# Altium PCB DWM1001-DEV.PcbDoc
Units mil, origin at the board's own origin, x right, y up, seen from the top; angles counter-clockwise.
Board outline 1692.91 x 2125.98 mil, 4 copper layers (Top Layer, Signal Layer 1, Signal Layer 2, Bottom Layer), stack 30.634 mil thick; 85 components, 72 nets, 323 pads, 369 vias.
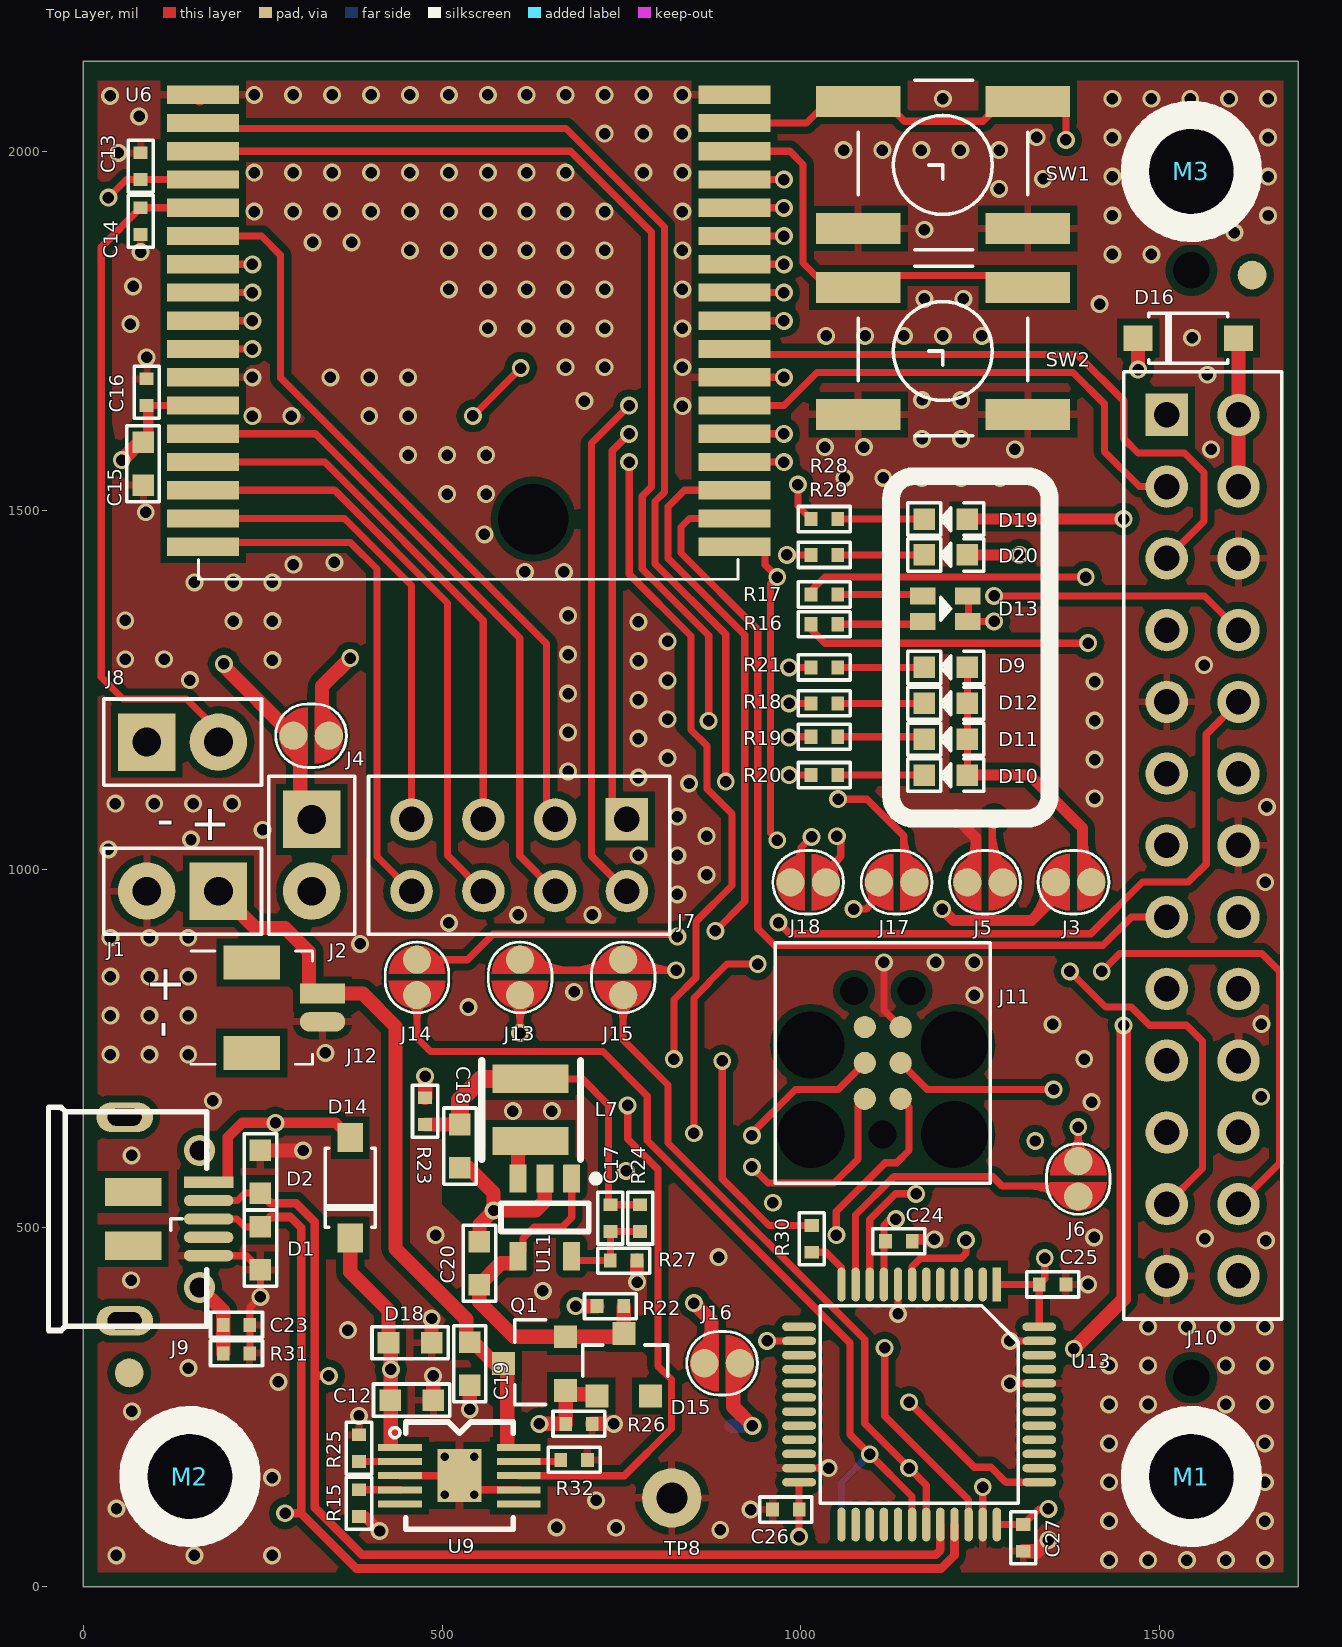
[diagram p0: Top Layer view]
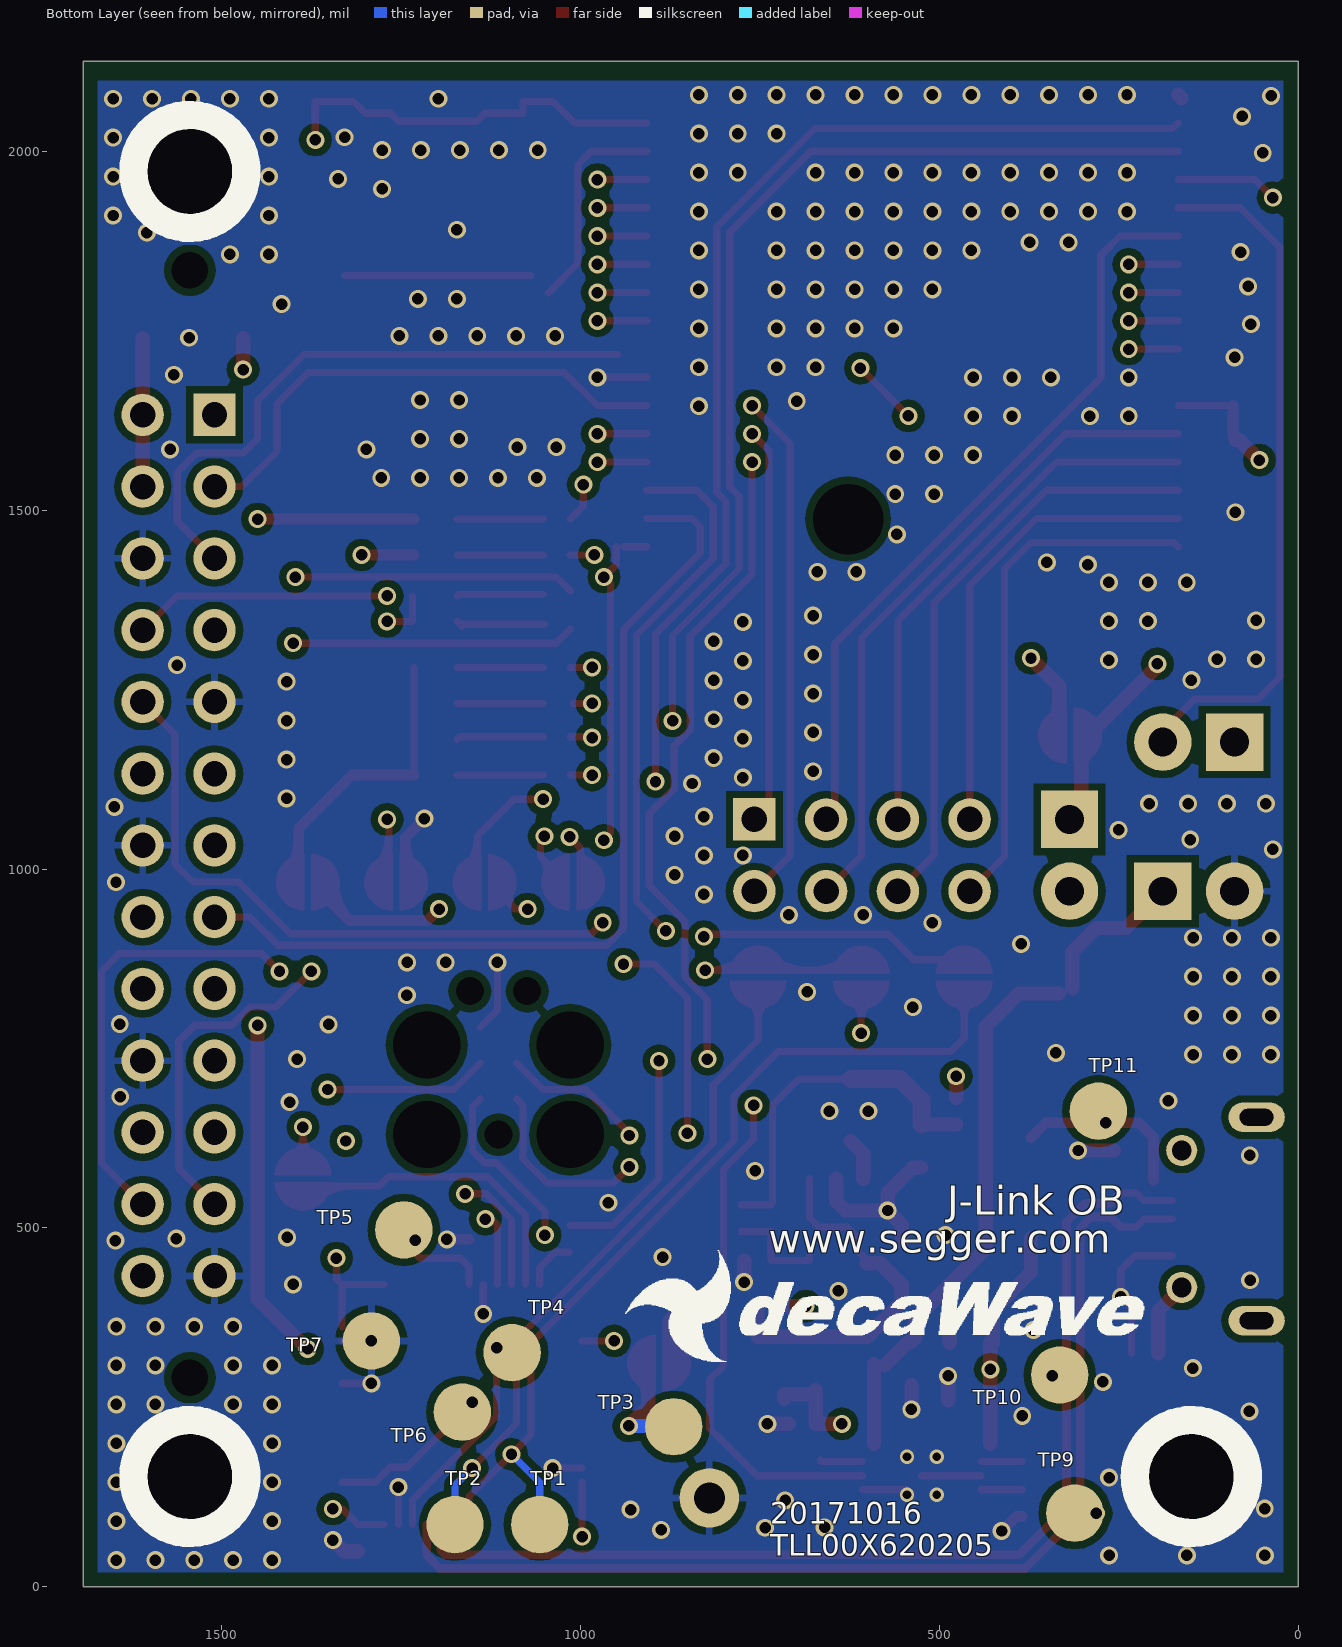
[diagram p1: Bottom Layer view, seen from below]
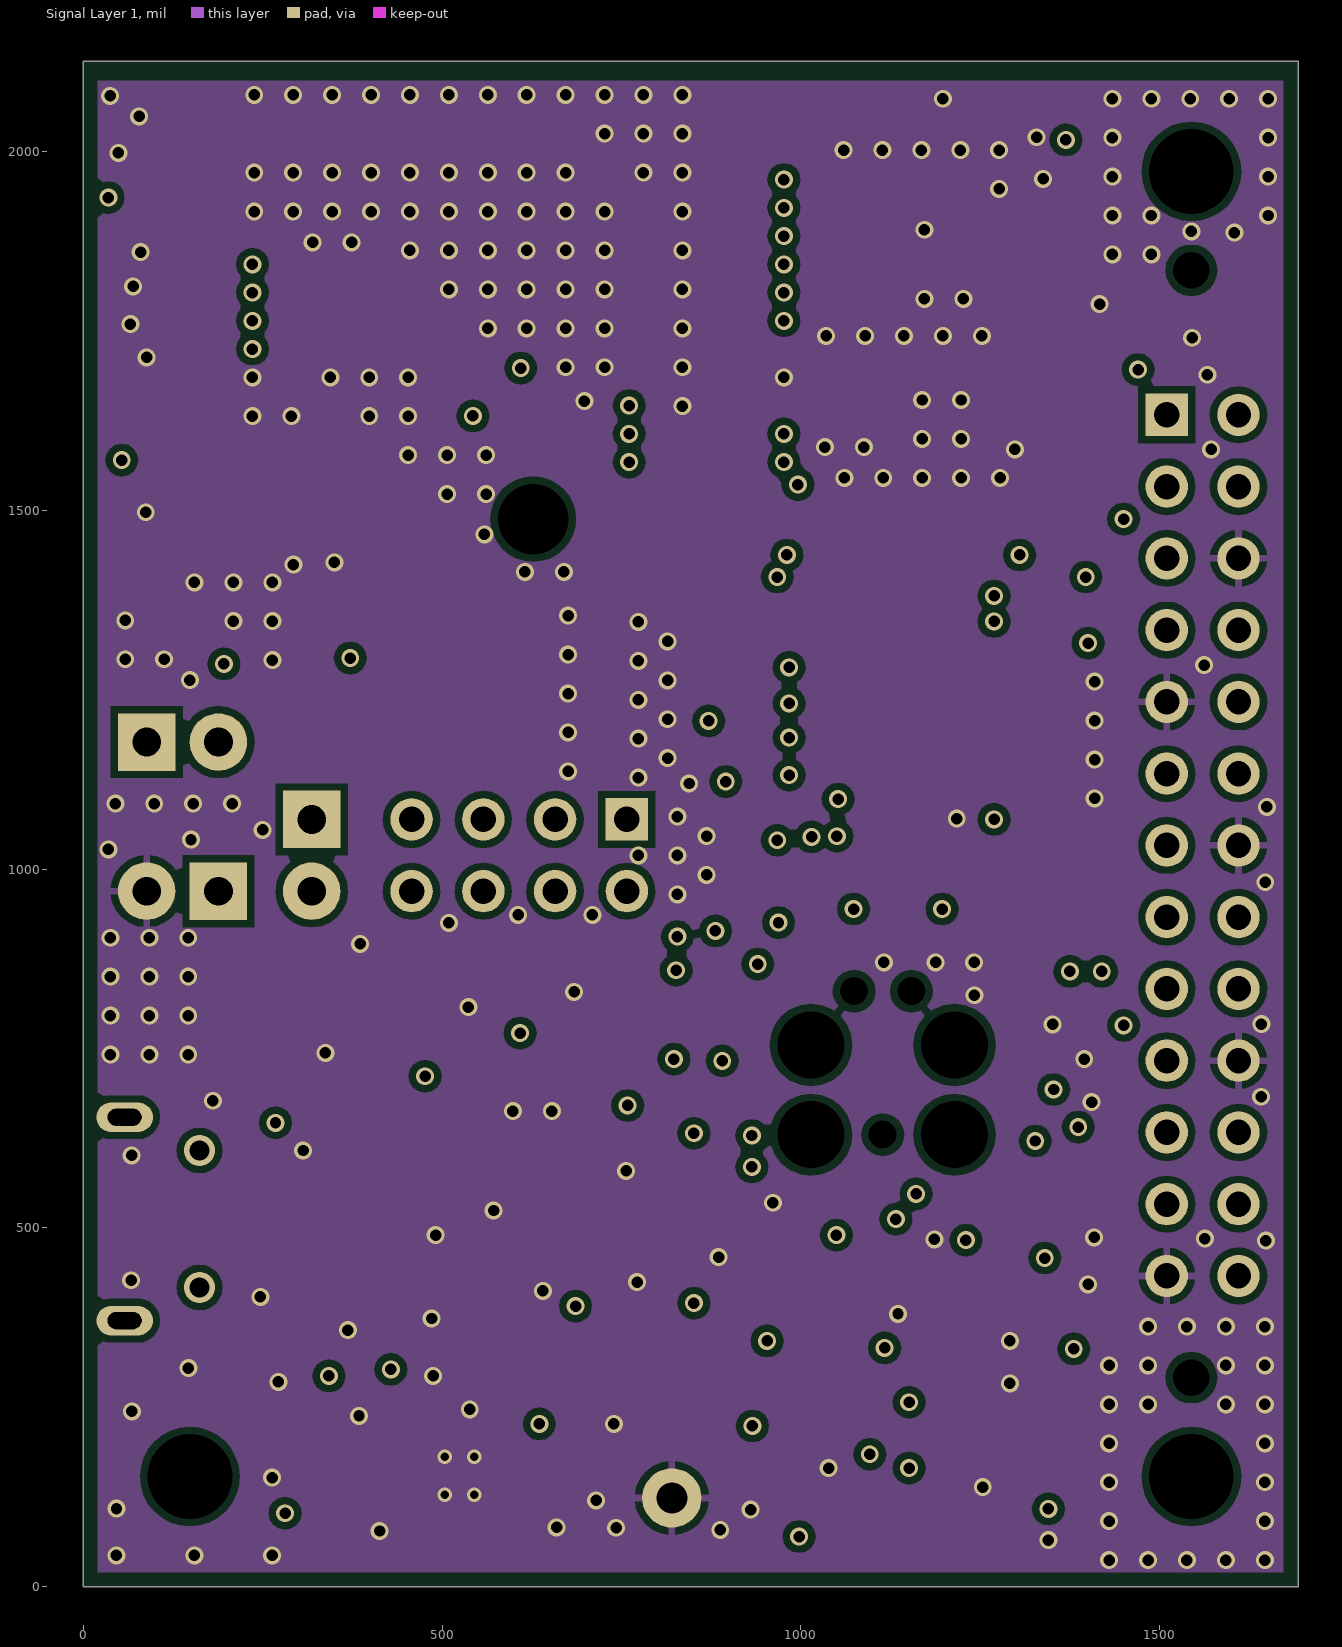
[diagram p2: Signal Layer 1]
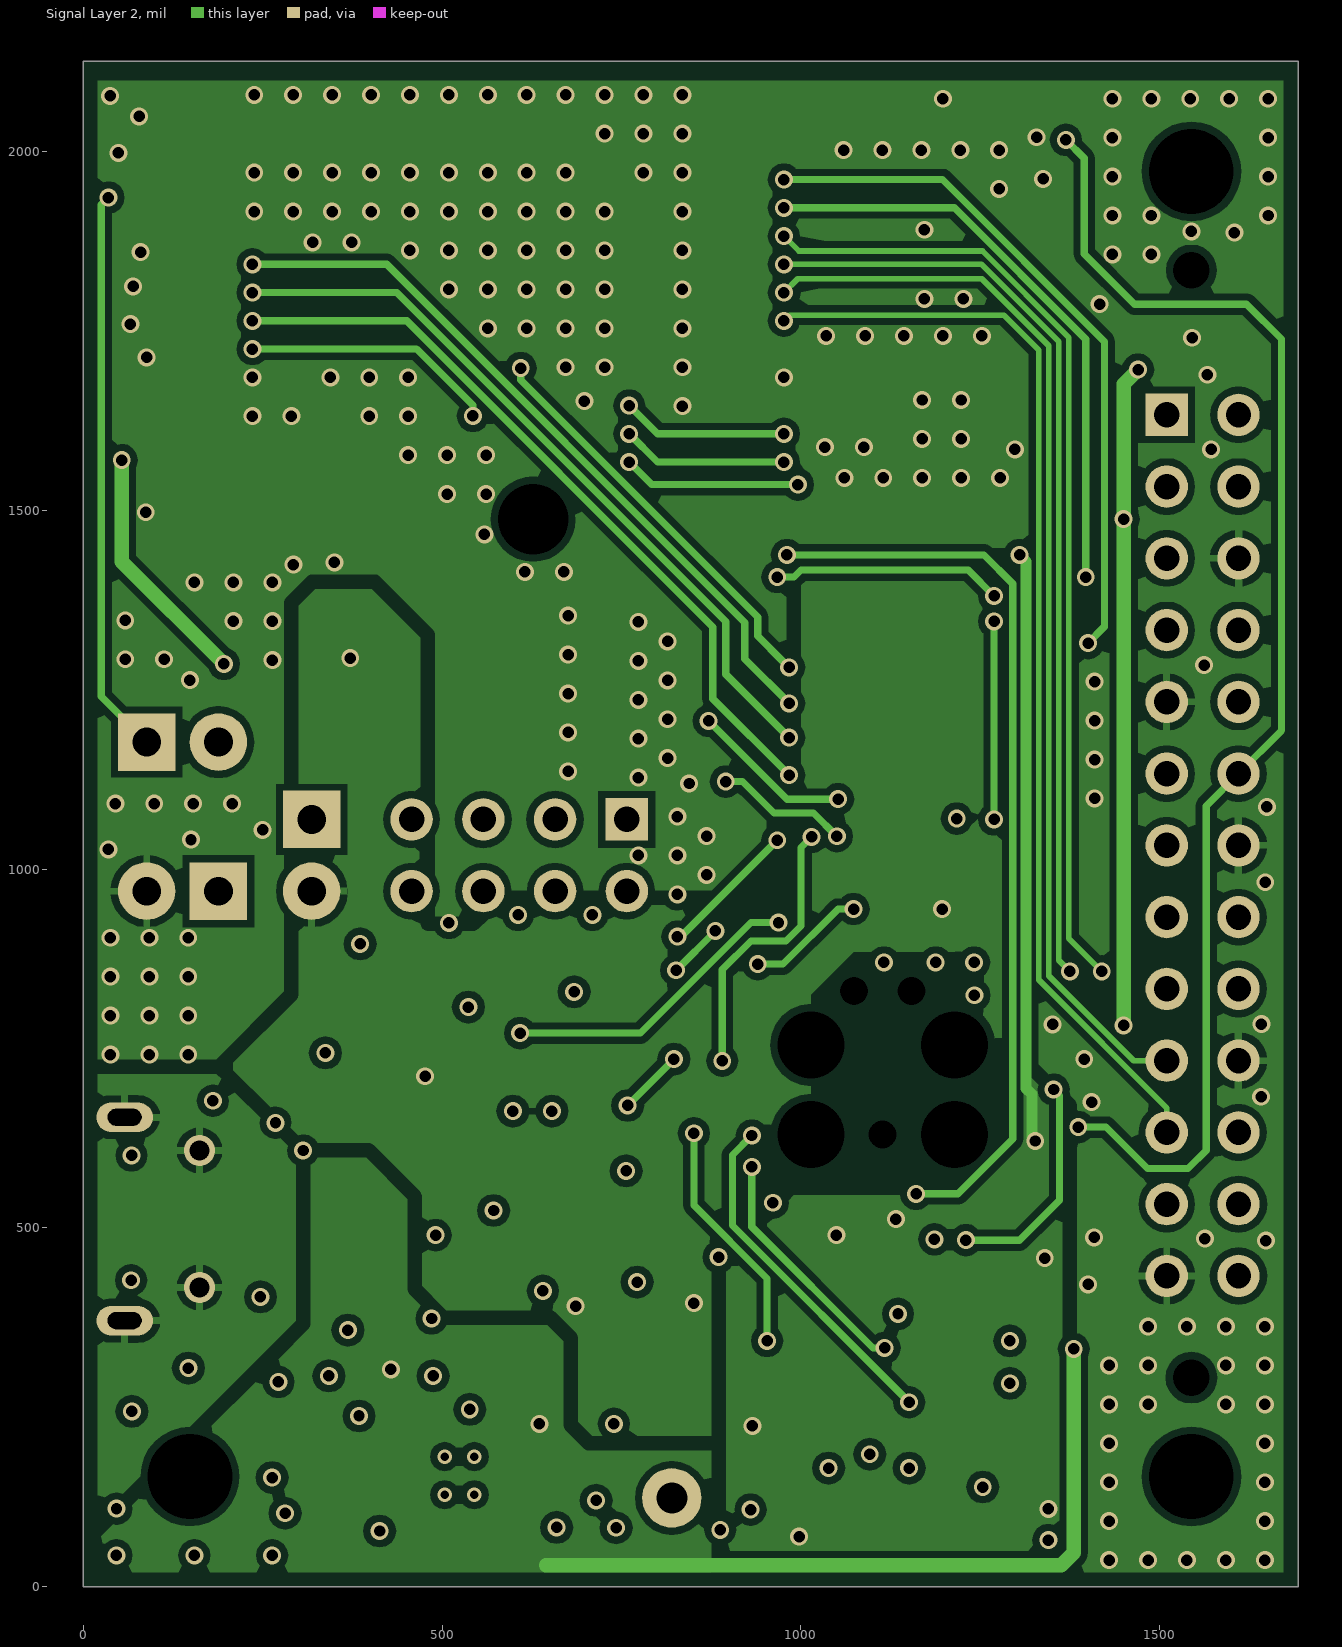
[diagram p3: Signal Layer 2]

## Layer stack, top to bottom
Top Solder: solder mask 0.4, Solder Resist, Dk 3.5
Top Layer: signal copper 1.4
Dielectric 1: core 10, FR-4, Dk 4.2
Signal Layer 1: signal copper 1.417
Dielectric 3: prepreg 5, Dk 4.2
Signal Layer 2: signal copper 1.417
Dielectric 2: core 10, Dk 4.2
Bottom Layer: signal copper 1.4
Bottom Solder: solder mask 0.4, Solder Resist, Dk 3.5

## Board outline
0,0 1692.91,0 1692.91,2125.98 0,2125.98

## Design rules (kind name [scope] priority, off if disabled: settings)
Clearance [All] p1: gap=6
Clearance Clearance_Route [All] p2 off: gap=8
Clearance Clearance_GND [All] p3 off: gap=10
ComponentClearance [All] p1 off: gap=10 collisioncheckmode=3 verticalgap=10 showdistances=FALSE
HoleSize [All] p1: absolutevalues=TRUE maxlimit=200 minlimit=1 maxpercent=80.000 minpercent=20.000
MinimumSolderMaskSliver [All] p1 off: minsoldermaskwidth=10
NetAntennae [All] p1 off: netantennaetolerance=0
PasteMaskExpansion [All] p1 off: expansion=0
PlaneConnect [All] p1: planeconnectstyle=Direct reliefexpansion=20 reliefentries=4 reliefconductorwidth=10 reliefairgap=10
PolygonConnect PolygonConnect_DirectConnect [(InComponentClass('Direct Connect'))] p1: connectstyle=Direct reliefconductorwidth=10 reliefentries=4 polygonreliefangle="90 Angle" airgapwidth=10
PolygonConnect PolygonConnect_IsVia [isVia] p2: connectstyle=Direct reliefconductorwidth=10 reliefentries=4 polygonreliefangle="90 Angle" airgapwidth=10
PolygonConnect [All] p3: connectstyle=Relief reliefconductorwidth=10 reliefentries=4 polygonreliefangle="90 Angle" airgapwidth=10
RoutingVias [All] p1: holewidth=16 width=25 viastyle="Through Hole" minholewidth=5 minwidth=10 maxholewidth=50 maxwidth=100
SilkToBoardRegionClearance [All] p1 off:
SilkToSilkClearance [All] p1 off: silktosilkclearance=10
SilkToSolderMaskClearance [IsPad] p1 off: minsilkscreentomaskgap=10 clearancetoexposedcopper=TRUE
SolderMaskExpansion [All] p1 off: expansion=4
Width [All] p1: maxlimit=50 minlimit=6 preferedwidth=10
20 further rules are at their usual default settings.

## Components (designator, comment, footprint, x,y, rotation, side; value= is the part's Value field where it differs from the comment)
C12 "4U7" C-SMT-0603 457.58,260.02 r0 top
C13 "330P" C-SMT-0402 80,1979.72 r270 top
C14 "330P" C-SMT-0402 80,1903.15 r90 top
C15 "10U" C-SMT-0603 83.43,1565 r270 top
C16 "100N" C-SMT-0402 88.43,1664.76 r90 top
C17 "22P" C-SMT-0402 734.61,513.84 r270 top
C18 "10U" C-SMT-0603 524.97,614.22 r270 top
C19 "4U7" C-SMT-0603 538.68,311.02 r270 top
C20 "4U7" C-SMT-0603 552.19,451.04 r90 top
C23 "100N" C-SMT-0402 213.6,365 r0 top
C24 "1U" C-SMT-0402 1136.65,481.48 r0 top
C25 "100N" C-SMT-0402 1350.91,421.3 r0 top
C26 "100N" C-SMT-0402 979.07,107.58 r180 top
C27 "100N" C-SMT-0402 1310,68.06 r270 top
D1 "5V ESD" C-SMT-0603 247,471.55 r90 top
D2 "5V ESD" C-SMT-0603 247,578.55 r270 top
D9 "G" LED-SMT-0603 1202.11,1281.15 r270 top
D10 "B" LED-SMT-0603 1202.11,1131.15 r270 top
D11 "R" LED-SMT-0603 1202.11,1181.15 r270 top
D12 "R" LED-SMT-0603 1202.11,1231.15 r270 top
D13 "DUAL LED" LED_DUAL 1232.78,1380.78 r180 top
D14 "PMEG4020ER" DIO_SOD123 372.1,556.05 r270 top
D15 "PMEG2005ET" DIO_SOT23 753.33,309.35 r0 top
D16 "PMEG4020ER" DIO_SOD123 1540,1740 r180 top
D18 "5V ESD" C-SMT-0603 455.4,340 r180 top
D19 "R" LED-SMT-0603 1202.11,1487.91 r270 top
D20 "R" LED-SMT-0603 1202.11,1437.91 r270 top
J1 "BATT CON" CON-100MIL-02 188.43,969.43 r180 top
J2 "CON02" CON-100MIL-02 318.39,1069.37 r270 top
J3 "SHORT" PAD_JUMPER 1375,981.85 r0 top
J4 "SHORT" PAD_JUMPER 322.56,1186.15 r180 top
J5 "SHORT" PAD_JUMPER 1251.76,981.68 r0 top
J6 "SHORT" PAD_JUMPER 1386.66,573.44 r270 top
J7 "CON(2X05)" CON-100MIL-2X04 757.56,1069.37 r270 top
J8 "NFC CON" CON-100MIL-02 88.43,1177.15 r0 top
J9 "USB_MICRO" USB_MICRO_U6F05E-CXT2-B15 122.17,512.6 r270 top
J10 "RPI Header" CON-100MIL-2X13 1510,1633.18 r0 top locked
J11 "TC2030-IDC" JLINK_6PIN_ADAPTOR 1114.2,630 r90 top
J12 "BATT CON" SH02AYS 333.43,826.69 r270 top
J13 "SHORT" PAD_JUMPER 608.79,854.22 r270 top
J14 "SHORT" PAD_JUMPER 465.17,854.22 r270 top
J15 "SHORT" PAD_JUMPER 752.42,854.22 r270 top
J16 "SHORT" PAD_JUMPER 885.39,311.49 r0 top
J17 "SHORT" PAD_JUMPER 1138.53,981.68 r180 top
J18 "SHORT" PAD_JUMPER 1015.29,981.68 r180 top
L7 "2U2H" IND_SDB3015 623.33,621.21 r90 top
M1 "mt_hole" "MT_HOLE_3MM - NPTH" 1544.29,153.54 r0 top
M2 "mt_hole" "MT_HOLE_3MM - NPTH" 148.62,153.54 r0 top
M3 "mt_hole" "MT_HOLE_3MM - NPTH" 1544.29,1972.44 r0 top
Q1 "AO3407A" FET_SOT23_GSD 628.96,311.04 r90 top
R15 "DNF" R-SMT-0402 384.32,116.54 r90 top
R16 "820R" R-SMT-0402 1032.79,1341.42 r0 top
R17 "150R" R-SMT-0402 1032.79,1382.83 r0 top
R18 "1K8" R-SMT-0402 1032.79,1231.15 r180 top
R19 "1K8" R-SMT-0402 1032.71,1184.53 r180 top
R20 "1K5" R-SMT-0402 1032.71,1131.15 r180 top
R21 "1K8" R-SMT-0402 1032.79,1281.15 r180 top
R22 "DNF" R-SMT-0402 734.73,391.04 r180 top
R23 "0R" R-SMT-0402 476.41,662.82 r90 top
R24 "69.8K 1%" R-SMT-0402 776.1,513.84 r90 top
R25 "1.8K 1%" R-SMT-0402 384.32,193.11 r270 top
R26 "100K" R-SMT-0402 690.87,227.04 r180 top
R27 "15K 1%" R-SMT-0402 753.21,454.53 r180 top
R28 "2K7" R-SMT-0402 1032.79,1487.91 r180 top
R29 "1K8" R-SMT-0402 1032.79,1437.91 r0 top
R30 "220R" R-SMT-0402 1015.27,484.8 r270 top
R31 "10K" R-SMT-0402 213.6,325.3 r0 top
R32 "10K" R-SMT-0402 684.2,176.92 r180 top
SW1 "TS-06MN" TS-1143S 1316.13,2070 r180 top
SW2 "TS-06MN" TS-1143S 1316.13,1810.73 r180 top
TP1 "TXD" PAD/R40MIL-SMD 1056.72,86.66 r90 bottom
TP2 "RXD" PAD/R40MIL-SMD 1174.83,86.66 r90 bottom
TP3 "3V4_SEGGER" PAD/R40MIL-SMD 870,222.96 r0 bottom
TP4 "SWDIO_OB" PAD/R40MIL-SMD 1095.25,326.34 r0 bottom
TP5 "#RESET_OB" PAD/R40MIL-SMD 1246.14,497.4 r0 bottom
TP6 "SWCLK_OB" PAD/R40MIL-SMD 1164.63,243.49 r90 bottom
TP7 "GND" PAD/R40MIL-SMD 1291.29,342.56 r0 bottom
TP8 "GND LOOP CONNECTOR" TP_LOOP_CONNECTOR 820.28,123.83 r0 top
TP9 "D+" PAD/R40MIL-SMD 311.14,102.72 r90 bottom
TP10 "D-" PAD/R40MIL-SMD 331.99,295.13 r90 bottom
TP11 "VUSB" PAD/R40MIL-SMD 278.17,662.82 r90 bottom
U6 "DWM1001" LM1_E1 160.69,1404.04 r0 top locked
U9 "BQ24092DGQ" "IC_MSOP10 - TI - DGQ" 524.32,154.83 r0 top
U11 "RT8059" SOT23-5 643.33,514.7 r270 top
U13 "STM32F072CBT6" IC_LQFP48 1164.99,253.98 r270 top locked

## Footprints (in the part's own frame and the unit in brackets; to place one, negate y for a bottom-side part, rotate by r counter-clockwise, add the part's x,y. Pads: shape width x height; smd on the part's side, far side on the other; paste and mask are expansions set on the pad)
C-SMT-0402 [mm] "Chip Resistor, 2-Leads, Body 1.00x0.50mm, IPC Medium Density"
  rect 0.45x0.5 smd: 1(-0.472,0) 2(0.472,0)
  silkscreen extent -0.92,-0.44 0.92,0.44, body extent -0.5,-0.3 0.5,0.3, height 0.2
C-SMT-0603 [mil] "Chip Resistor, 2-Leads, Body 1.60x0.80mm, IPC Medium Density"
  rect 30x30 smd: 1(-30,0) 2(30,0)
  silkscreen extent -53,-22 53,22, body extent -52,-20 51,19, height 35
CON-100MIL-02 [mil]
  rect 80x80 hole 40: 1(0,0)
  round 80 hole 40: 2(100,0)
  silkscreen extent -60,-60 160,60
CON-100MIL-2X04 [mm]
  rect 1.5x1.5 hole 0.9: 1(0,0)
  round 1.5 hole 0.9: 2(2.54,0) 3(0,-2.54) 4(2.54,-2.54) 5(0,-5.08) 6(2.54,-5.08) 7(0,-7.62) 8(2.54,-7.62)
  silkscreen extent -1.52,-9.14 4.06,1.52
CON-100MIL-2X13 [mm]
  rect 1.5x1.5 hole 0.9: 1(0,0)
  round 1.5 hole 0.9: 2(2.54,0) 3(0,-2.54) 4(2.54,-2.54) 5(0,-5.08) 6(2.54,-5.08) 7(0,-7.62) 8(2.54,-7.62) 9(0,-10.16) 10(2.54,-10.16) 11(0,-12.7) 12(2.54,-12.7) 13(0,-15.24) 14(2.54,-15.24) 15(0,-17.78) 16(2.54,-17.78) 17(0,-20.32) 18(2.54,-20.32) 19(0,-22.86) 20(2.54,-22.86) 21(0,-25.4) 22(2.54,-25.4) 23(0,-27.94) 24(2.54,-27.94) 25(0,-30.48) 26(2.54,-30.48)
  silkscreen extent -1.52,-32 4.06,1.52
DIO_SOD123 [mil]
  rect 40x35 smd: 1(-70,0) 2(70,0)
  silkscreen extent -55,-35 55,35, body extent -73,-31 73,32, height 47
DIO_SOT23 [mil]
  rect 32x32 smd: 1(-37.4,-43.31) 2(0,43.31) NC(37.4,-43.31)
  silkscreen extent -57,-16 61,28, body extent -56,-55 58,55, height 51
FET_SOT23_GSD [mil]
  rect 32x32 smd: D(0,43.31) G(-37.4,-43.31) S(37.4,-43.31)
  silkscreen extent -57,-16 61,28, body extent -56,-55 58,55, height 47
IC_LQFP48 [mm]
  rect 1.2x0.3 smd: 1(-4.25,2.75)
  oval 1.2x0.3 smd: 2(-4.25,2.25) 3(-4.25,1.75) 4(-4.25,1.25) 5(-4.25,0.75) 6(-4.25,0.25) 7(-4.25,-0.25) 8(-4.25,-0.75) 9(-4.25,-1.25) 10(-4.25,-1.75) 11(-4.25,-2.25) 12(-4.25,-2.75) 25(4.25,-2.75) 26(4.25,-2.25) 27(4.25,-1.75) 28(4.25,-1.25) 29(4.25,-0.75) 30(4.25,-0.25) 31(4.25,0.25) 32(4.25,0.75) 33(4.25,1.25) 34(4.25,1.75) 35(4.25,2.25) 36(4.25,2.75)
  oval 0.3x1.2 smd: 13(-2.75,-4.25) 14(-2.25,-4.25) 15(-1.75,-4.25) 16(-1.25,-4.25) 17(-0.75,-4.25) 18(-0.25,-4.25) 19(0.25,-4.25) 20(0.75,-4.25) 21(1.25,-4.25) 22(1.75,-4.25) 23(2.25,-4.25) 24(2.75,-4.25) 37(2.75,4.25) 38(2.25,4.25) 39(1.75,4.25) 40(1.25,4.25) 41(0.75,4.25) 42(0.25,4.25) 43(-0.25,4.25) 44(-0.75,4.25) 45(-1.25,4.25) 46(-1.75,4.25) 47(-2.25,4.25) 48(-2.75,4.25)
  silkscreen extent -3.5,-3.5 3.5,3.5, body extent -4.5,-4.5 4.5,4.5, height 1.6
"IC_MSOP10 - TI - DGQ" [mm] "MSOP10 WITH THERMAL PAD TI DGQ PACKAGE"
  rect 1.57x1.88 smd: 0(0,0)
  rect 1.55x0.25 smd: 1(-2.1,1) 2(-2.1,0.5) 3(-2.1,0) 4(-2.1,-0.5) 5(-2.1,-1) 6(2.1,-1) 7(2.1,-0.5) 8(2.1,0) 9(2.1,0.5) 10(2.1,1)
  silkscreen extent -2.46,-1.9 1.9,1.9, body extent -2.52,-1.55 2.52,1.55, height 1.1
IND_SDB3015 [mm]
  rect 1x2.7 smd: 1(0,0) 2(2.2,0)
  silkscreen extent -0.66,-1.77 2.84,1.73, body extent -0.41,-1.52 2.59,1.48, height 1.5
JLINK_6PIN_ADAPTOR [mm]
  round 0.787 smd paste-10: 1(1.27,-0.635) 2(1.27,0.635) 3(2.54,-0.635) 4(2.54,0.635) 5(3.81,-0.635) 6(3.81,0.635)
  round 0 hole 2.375 unplated: ""(0,2.54) ""(0,-2.54) ""(3.175,-2.54) ""(3.175,2.54)
  round 0 hole 0.991 unplated: ""(0,0) ""(5.08,-1.016) ""(5.08,1.016)
  silkscreen extent -1.71,-3.81 6.79,3.81
LED-SMT-0603 [mil]
  rect 30x30 smd: A(0,30) K(0,-30)
  silkscreen extent -23,-53 23,53, body extent -15,-34 16,33, height 26
LED_DUAL [mm] "19-22_VRVGC/TR8"
  rect 0.9x0.6 smd: 1(1.6,0.9) 2(0,0.9) 3(1.6,0) 4(0,0)
  silkscreen extent 0.6,0.05 0.96,0.86, body extent 0,-0.2 1.6,1.1, height 0.32
LM1_E1 [mm] "LM1_E1 Chip antennas"
  rect 2.54x0.65 smd: 1(0.16,17.15) 2(0.16,16.15) 3(0.16,15.15) 4(0.16,14.15) 5(0.16,13.15) 6(0.16,12.15) 7(0.16,11.15) 8(0.16,10.15) 9(0.16,9.15) 10(0.16,8.15) 11(0.16,7.15) 12(0.16,6.15) 13(0.16,5.15) 14(0.16,4.15) 15(0.16,3.15) 16(0.16,2.15) 17(0.16,1.15) 18(18.97,1.15) 19(18.97,2.15) 20(18.97,3.15) 21(18.97,4.15) 22(18.97,5.15) 23(18.97,6.15) 24(18.97,7.15) 25(18.97,8.15) 26(18.97,9.15) 27(18.97,10.15) 28(18.97,11.15) 29(18.97,12.15) 30(18.97,13.15) 31(18.97,14.15) 32(18.97,15.15) 33(18.97,16.15) 34(18.97,17.15)
  silkscreen extent 0,0 19.1,0.7, body extent 0,0 19.13,26.1, height 4.6
"MT_HOLE_3MM - NPTH" [mm] "3mm Mt hole"
  round 0 hole 3 unplated: 1(0,0)
  silkscreen extent -2,-2 2,2
PAD/R40MIL-SMD [mil]
  round 80 smd: 1(0,0)
PAD_JUMPER [mm] "SOLDER BRIDGE JUMPER"
  round 1 smd mask-15: 1(-0.5,0) 2(0.754,0)
  Top Layer region: 0.254,-1 0.254,1 0.688,0.901 1.036,0.623 1.229,0.223 1.229,-0.223 1.036,-0.623 0.688,-0.901 0.254,-1
  Top Layer region: 0,-1 -0.434,-0.901 -0.782,-0.623 -0.975,-0.223 -0.975,0.223 -0.782,0.623 -0.434,0.901 0,1 0,1
  silkscreen extent -1.13,-1.13 1.38,1.13
R-SMT-0402 [mm] "Chip Resistor, 2-Leads, Body 1.00x0.50mm, IPC Medium Density"
  rect 0.45x0.5 smd: 1(-0.472,0) 2(0.472,0)
  silkscreen extent -0.92,-0.44 0.92,0.44, body extent -0.5,-0.25 0.5,0.25, height 0.35
SH02AYS [mm]
  rect 1.2x2 smd: 0(-1.1,-2.5) 0(2.1,-2.5)
  rect 0.7x1.6 smd: 1(0,0)
  oval 0.7x1.6 smd: 2(1,0)
  silkscreen extent -1.5,-4.65 2.5,-0.35, body extent -1.5,-4.58 2.5,0.47, height 3.15
SOT23-5 [mm] "SOT23, 5-Leads, Body 2,90x2,80mm, Pitch 0,95mm, IPC Medium Density"
  rrect5% 1x0.6 smd: 1(-1.375,0.95) 2(-1.375,0) 3(-1.375,-0.95) 4(1.375,-0.95) 5(1.375,0.95)
  silkscreen extent -1.5,-1.55 0.5,1.93, body extent -1.5,-1.53 1.5,1.53, height 1.45
TP_LOOP_CONNECTOR [mm]
  round 2.1 hole 1.1: 1(0,0)
  body extent -1.7,-1.42 1.65,1.58, height 5.36
TS-1143S [mm]
  rect 3x1.1 smd: 1(0,0) 2(6,0) 3(0,4.5) 4(6,4.5)
  silkscreen extent 0,-0.75 6,5.25, body extent -0.25,-1.01 6.25,5.49, height 7
USB_MICRO_U6F05E-CXT2-B15 [mm]
  rect 0.4x1.75 smd: 1(-1.3,1.338)
  oval 0.4x1.75 smd: 2(-0.65,1.338) 3(0,1.338) 4(0.65,1.338) 5(1.3,1.338)
  rect 1x2 smd: 6(-0.95,-1.338) 6(0.95,-1.338)
  oval 1.05x2 hole 0.6 slot 1.2 at 90 deg: A(-3.6,-1.637) B(3.6,-1.637)
  round 1.1 hole 0.7: C(-2.425,1.013) D(2.425,1.013)
  silkscreen extent -3.95,-4.34 3.95,1.26, body extent -3.94,-4.37 3.96,1.38, height 2.7

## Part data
C12 C13 C14 C15 C16 C17 C18 C19 C20 C23 C24 C25 C26 C27: library part C-SMT-0402, "*C-SMT-0402"
D1 D2 D14 D15 D16 D18: library part DIODE_SCHOTTKY, "Diode"
D9 D10 D11 D12 D19 D20: library part LED, "LED"
D13: library part LED_X2
J1 J8 J12: library part CON02, "2 pin Connector"
J2: "2 pin Connector"
J3 J4 J5 J6 J13 J14 J15 J16 J17 J18: library part JUMPER_OPEN
J7: library part CON(2X04)_1
J9: library part CON05_USB_2, "USB-MR1-05-TH-MB"
J10: library part RPI_HEADER_SHORT
J11: "J-Link 6-pin Programming Pads"
L7: library part L, "INDUCTOR"
Q1: library part MOSFET-P1, "P-MOSFET"
R15 R16 R17 R18 R19 R20 R21 R22 R23 R24 R25 R26 R27 R28 R29 R30 R31 R32: library part R-SMT-0402, "*R-SMT-0402"
SW1 SW2: library part TACT_SW/4PIN
TP1 TP2 TP3 TP4 TP5 TP6 TP7 TP8 TP9 TP10 TP11: library part "TEST POINT_1", "TEST POINT"
U6: library part LM1_E1
U13: library part STM32F072CxU6, "J-LINK MCU"

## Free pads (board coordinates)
  round 60 smd far side: 0(-108.18,4773.43) 0(-108.18,206.61) 0(5619.65,206.61) 0(5619.65,4773.46)
  round 60 smd: 0(-108.18,4891.54) 0(-108.18,88.5) 0(5619.65,88.5) 0(5619.65,4891.57)
  round 40 smd: 0(64,298) 0(1628.91,1828.01)
  round 0 hole 98.43 unplated: 0(627.03,1487.89)
  round 3.94 hole 51.18 unplated mask-590.55: 0(1544.29,291.34) 0(1544.29,1834.65)
  round 0 hole 118.11 unplated: 1(-108.18,5088.37) 1(-108.18,-108.34) 1(5619.65,-108.34) 1(5619.65,5088.4)

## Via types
v1: diameter 25, hole 16, Top Layer to Bottom Layer, tented both sides, 365 vias
v2: diameter 20, hole 12, Top Layer to Bottom Layer, 4 vias

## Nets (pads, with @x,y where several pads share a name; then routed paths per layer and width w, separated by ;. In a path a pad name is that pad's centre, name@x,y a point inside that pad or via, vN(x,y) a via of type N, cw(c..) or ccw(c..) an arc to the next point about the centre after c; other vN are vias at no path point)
3V4: J2.2 J3.1 J4.1 J16.1 R22.2 R23.2 | length 682.3
  Top Layer w15: v1(1196.86,944.48) 1212.87,928.47 1321.79,928.47 ; J3.1@1343.13,981.59 cw(c1270.23,980.03) 1321.79,928.47 ; 1346.65,953.32 ccw(c1318.9,981.07) J3.1@1358.13,981.91 ; J3.1@1349.8,970.98 cw(c1345.23,961.99) 1355.31,961.99 ; J3.1 1355.31,961.99 ; J3.1@1360.83,970.98 ccw(c1365.4,961.99) 1355.32,961.99 ; 1321.79,928.47 1355.31,961.99
  Top Layer w20: J4.1@332.83,1185.98 332.83,1254.88 v1(372.1,1294.15) ; 332.83,1232.24 ccw(c388.33,1232.24) J4.1@349.09,1192.99 ; R23.2 v1(476.41,711.48) ; v1(686.07,391.04) R22.2 ; v1(851.1,395.22) 875.55,370.77 875.55,321.34 J16.1 ; J16.1@858.86,318.34 ccw(c818.55,358.65) 875.55,358.65
3V4_SEGGER: C24.1 C25.1 C26.1 C27.1 D20.A J11.1 J16.2 TP3.1 U13.1 U13.9 U13.24 U13.36 U13.48 | length 1737.2
  Top Layer w10: v1(997.67,70) C26.1 U13.24 ; v1(1049.5,490) 1049.5,522.98 1117.55,591.03 1133.67,591.03 1150.65,608 1150.65,668.56 J11.1 ; U13.9 1115.78,504.21 1123.84,512.27 v1(1132.6,512.27) ; U13.36 C27.1 1331.81,108.47 v1(1345,108.47) ; U13.1 C25.1 ; U13.48 C25.1 ; v1(1340,458.15) 1340,428.99 C25.1
  Top Layer w15: D20.A v1(1304.93,1437.91)
  Top Layer w20: 905.67,265.4 cw(c961.17,265.4) J16.2@921.92,304.64 ; J16.2 905.67,302.08 905.67,251 v1(932.6,224.07)
  Signal Layer 2 w15: v1(1304.93,1437.91) 1313.97,1428.88 1313.97,694.54 1322.06,686.44 1322.06,625.9 v1(1326.74,621.21)
  Bottom Layer w20: TP3.1@903.81,224.07 v1(932.6,224.07)
5V: C12.1 D14.2 D15.1 D16.2 D18.2 D19.A Q1.G R26.2 U9.1 | length 3132.3
  Top Layer w15: D19.A v1(1450,1487.91)
  Top Layer w20: D14.2 372.1,438.66 425.4,385.35 D18.2 ; 428.68,199.34 v1(428.68,303.02) D18.2@428.68,340 ; v1(635.56,227.04) R26.2 Q1.G@672.27,268.17 ; Q1.G Q1.G@672.27,268.17 ; D15.1@715.93,261.83 715.93,268.17 Q1.G@672.27,268.17 ; v1(1380.35,331.46) 1450,401.11 v1(1450,782.41) ; v1(1470,1696.18) D16.2
  Signal Layer 2 w20: 645,30 1362.96,30 1380.35,47.39 v1(1380.35,331.46) ; v1(1450,782.41) 1450,1676.18 v1(1470,1696.18)
#RESET_OB: J11.3 TP5.1 U13.7 | length 653.6
  Top Layer w10: J11.3 1176.2,693 v1(1352.27,693) ; U13.7 1155.15,446.07 1167,457.92 1223.32,457.92 1230,464.61 v1(1230,483)
  Signal Layer 2 w10: v1@1242,483 1304.93,483 1360.67,538.74 1360.67,684.6 v1(1352.27,693)
CS_RPI: J10.24 U6.29 | length 2043.7
  Top Layer w10: U6.29 v1(976.42,1882.38) ; v1(1419.39,857.56) 1444.12,882.3 1642.7,882.3 1667.44,857.56 1667.44,590.62 J10.24
  Signal Layer 2 w8: v1(976.42,1882.38) 997.31,1861.48 1253.09,1861.48 1373.47,1741.11 1373.47,903.49 v1(1419.39,857.56)
CTS: U13.17
D+: D1.2 J9.3 TP9.1 U13.33 | length 1558.5
  Top Layer w10: J9.3 214.38,512.6 225.43,501.55 D1.2
  Top Layer w12: D1.2 260.83,515.38 288.74,515.38 303.56,500.56 303.56,102.44 ; v1(281.27,102.44) 303.56,102.44 ; U13.33 1214.2,43.82 1195.88,25.5 380.49,25.5 303.56,102.44
D-: D2.2 J9.2 TP10.1 U13.32 | length 1524.2
  Top Layer w10: J9.2 214.93,538.19 225.29,548.55 D2.2
  Top Layer w12: D2.2 261.17,534.38 296.61,534.38 322.56,508.43 322.56,293.87 ; v1(342.41,293.87) 322.56,293.87 ; U13.32 1194.52,51.01 1188.01,44.5 388.36,44.5 322.56,110.31 322.56,293.87
EARTH: C23.1 J9.A J9.B J9.C J9.D R31.1 | length 105.5
  Top Layer w20: J9.D 195,384.17 C23.1 R31.1
GND: C12.2 C13.1 C14.1 C15.2 C16.2 C18.2 C19.2 C20.2 C23.2 C24.2 C25.2 C26.2 C27.2 D1.1 D2.1 D18.1 J1.2 J5.1 J9.5 J10.6 J10.9 J10.14 J10.20 J10.25 J11.5 J12.2 R15.1 R25.1 R26.1 R27.1 R31.2 R32.1 SW1.3 SW1.4 SW2.3 SW2.4 TP7.1 TP8.1 U6.1 U6.11 U6.24 U6.34 U9.0 U9.3 U9.7 U11.2 U13.8 U13.23 U13.35 U13.44 U13.47 | length 1495.6
  Top Layer w10: J9.5 227.13,461.42 D1.1 v1(247,403.89) 232.2,389.09 C23.2 R31.2 ; U9.3 U9.0 ; U9.0@544,135.14 U9.7 ; U6.24 v1(976.42,1685.53) ; U13.23 v1(1038.69,165.4) ; v1(1115.78,870) 1115.78,803.43 J11.5 ; v1(1135.46,380.28) U13.8 ; U13.35 v1(1253.57,139) ; v1(1291.29,283.51) U13.44 ; v1(1291.29,342.56) U13.47
  Top Layer w15: R15.1 392.81,97.94 v1(413.03,77.73) ; C24.2@1155.25,484.24 v1(1186.15,484.24) ; v1(1217.37,1070.53) 1244.28,1043.62 1244.28,993.88 J5.1 ; J5.1@1223.46,990.29 ccw(c1173.19,1040.56) 1244.28,1040.56 ; J5.1@1234.07,979.69 ccw(c1209.41,1004.35) 1244.28,1004.35
  Top Layer w20: U6.1@162.38,2074.63 U6.1 ; D2.1@256.34,607.99 v1(306.54,607.99) ; D18.1 v1(485.4,373.85) ; C12.2 v1(487.58,293.87) ; C18.2 536.69,584.22 571.81,549.1 v1(571.81,524.37) ; v1(538.68,247.17) C19.2 ; C20.2 552.19,504.75 v1(571.81,524.37) ; U11.2 643.33,537.18 630.52,524.37 v1(571.81,524.37) ; R26.1 v1(739.52,227.04) ; v1(771.81,424.48) R27.1 ; C27.2 1329.46,49.46 v1(1345,65)
  other v1: 1429.71,37.19 1483.95,37.19 1538.2,37.19 1592.44,37.19 1646.69,37.19 46.29,43.63 154.78,43.63 263.27,43.63 887.71,79.4 742.6,82.28 659.82,82.78 1429.71,91.43 1646.69,91.43 930,107.58 46.37,108.78 714.7,120.45 1429.71,145.68 1646.69,145.68 263.27,152.12 1429.71,199.92 1646.69,199.92 384.32,238 67.68,244.52 1429.71,254.17 1483.95,254.17 1592.44,254.17 1646.69,254.17 272,285.5 146.54,304.75 1429.71,308.41 1483.95,308.41 1592.44,308.41 1646.69,308.41 368.82,357.71 1483.95,362.65 1538.2,362.65 1592.44,362.65 1646.69,362.65 640.61,412.24 1400.3,421.3 66.72,427.12 885.39,459.4 1648.19,482.33 1563.13,485.12 1408.8,486.94 491.22,490 961.12,535.12 756.55,579.69 67.3,601.18 598.85,662.82 653.1,662.82 1405.2,675.36 180.69,677.29 1641.36,682.88 1394.98,735.22 37.82,741.72 92.07,741.72 146.31,741.72 337.44,744.02 1350.95,783.85 1641.98,784.09 37.82,795.96 92.07,795.96 146.31,795.96 536.69,807.85 1242,824.36 684.2,829.15 37.82,850.2 92.07,850.2 146.31,850.2 1188.01,870 1241.61,870 385.93,895.87 37.82,904.45 92.07,904.45 146.31,904.45 509.63,925.05 605.93,936.36 709.47,936.36 827.96,964.87 1647.26,981.85 868.65,991.99 773.72,1019.11 827.96,1019.11 35.07,1027.51 150.18,1041.18 868.65,1046.24 249.97,1054.92 827.96,1073.36 1649.44,1086.78 44.74,1091.44 98.99,1091.44 153.23,1091.44 207.48,1091.44 1409.56,1098.57 844.3,1119.43 773.72,1127.6 675.86,1136.31 1409.56,1152.81 814.4,1154.72 773.72,1181.85 675.86,1190.55 1409.56,1207.05 814.4,1208.97 773.72,1236.09 675.86,1244.8 1409.56,1261.3 814.4,1263.21 148.62,1263.65 1562.2,1284.54 773.72,1290.33 263.5,1291.36 58.52,1292.61 112.76,1292.61 675.86,1299.04 814.4,1317.46 773.72,1344.58 209.26,1345.6 263.5,1345.6 58.52,1346.85 675.86,1353.28 155.01,1399.84 209.26,1399.84 263.5,1399.84 615.57,1414.31 669.82,1414.31 292.87,1424.35 350.08,1427.58 558.98,1466.72 87.14,1497.46 507.08,1522.8 561.33,1522.8 1060.65,1545.39 1114.9,1545.39 1169.14,1545.39 1223.38,1545.39 1277.63,1545.39 452.84,1577.04 507.08,1577.04 561.33,1577.04 1298.33,1585.05 1571.82,1585.05 1033.53,1588.29 1087.77,1588.29 1169.14,1599.64 1223.38,1599.64 235.86,1631.29 290.11,1631.29 398.6,1631.29 452.84,1631.29 835,1645.28 698.53,1652.43 1169.14,1653.88 1223.38,1653.88 235.86,1685.53 344.35,1685.53 398.6,1685.53 452.84,1685.53 1566.55,1689.06 672.27,1699.52 726.51,1699.52 835,1699.52 88.43,1713.21 1545.43,1740.59 1035.29,1743.12 1089.53,1743.12 1143.78,1743.12 1198.02,1743.12 1252.27,1743.12 563.78,1753.77 618.02,1753.77 672.27,1753.77 726.51,1753.77 835,1753.77 65.7,1759.6 1416.33,1787.42 1172.29,1794.86 1226.53,1794.86 509.54,1808.01 563.78,1808.01 618.02,1808.01 672.27,1808.01 726.51,1808.01 835,1808.01 69.58,1812.13 1434.26,1856.75 1488.51,1856.75 80,1860 455.29,1862.26 509.54,1862.26 563.78,1862.26 618.02,1862.26 672.27,1862.26 726.51,1862.26 835,1862.26 319.68,1873.6 373.93,1873.6 1604.2,1887.21 1544.29,1888.89 1172.29,1891.16 1434.26,1910.99 1488.51,1910.99 1651.24,1910.99 238.32,1916.5 292.56,1916.5 346.8,1916.5 401.05,1916.5 455.29,1916.5 509.54,1916.5 563.78,1916.5 618.02,1916.5 672.27,1916.5 726.51,1916.5 835,1916.5 1276.51,1948.01 1337.63,1962.1 1434.26,1965.24 1651.24,1965.24 238.32,1970.74 292.56,1970.74 346.8,1970.74 401.05,1970.74 455.29,1970.74 509.54,1970.74 563.78,1970.74 618.02,1970.74 672.27,1970.74 780.76,1970.74 835,1970.74 49.13,1998.32 1059.54,2002.25 1113.78,2002.25 1168.02,2002.25 1222.27,2002.25 1276.51,2002.25 1434.26,2019.48 1651.24,2019.48 1328.63,2020.05 726.51,2024.99 780.76,2024.99 835,2024.99 77.9,2049.05 1198.02,2073.72 1434.26,2073.72 1488.51,2073.72 1542.75,2073.72 1597,2073.72 1651.24,2073.72 37.43,2077.76 238.32,2079.23 292.56,2079.23 346.8,2079.23 401.05,2079.23 455.29,2079.23 509.54,2079.23 563.78,2079.23 618.02,2079.23 672.27,2079.23 726.51,2079.23 780.76,2079.23 835,2079.23
  other v2: 503.65,128.25 544.98,128.25 503.65,181.4 544.98,181.4
GPIO_RPI: J10.15 U6.19 | length 1279.2
  Top Layer w10: U6.19 844.96,1488.68 833,1476.72 833,1440.7 940,1333.7 940,917.26 963.3,893.97 1421.26,893.97 1460.47,933.18 J10.15
M_PIN6: J7.3 U6.6 | length 1063.8
  Top Layer w10: U6.6 248.25,1882.38 275,1855.63 275,1684.85 645.66,1314.19 645.66,1081.27 J7.3
M_PIN13: J7.4 U6.13 | length 932.5
  Top Layer w10: U6.13 323.88,1606.79 608.33,1322.34 608.33,1018.6 J7.4
M_PIN14: J7.5 U6.14 | length 759.1
  Top Layer w10: U6.14 336.45,1567.42 557.56,1346.32 J7.5
M_PIN15: J7.6 U6.15 | length 827.9
  Top Layer w10: U6.15 350.37,1528.05 507.5,1370.92 507.5,1019.43 J7.6
M_PIN16: J7.7 U6.16 | length 655.2
  Top Layer w10: U6.16 364.28,1488.68 457.56,1395.4 J7.7
M_PIN17: J7.8 U6.17 | length 729.1
  Top Layer w10: U6.17 173.09,1455.41 372.1,1455.41 409.22,1418.28 409.22,1017.7 J7.8
M_PIN21: J7.1 U6.21 | length 856.3
  Top Layer w10: J7.1 737.35,1089.58 737.35,1583.27 v1(760.88,1606.79) ; U6.21 v1(976.42,1567.42)
  Signal Layer 2 w10: v1(760.88,1606.79) 800.25,1567.42 v1(976.42,1567.42)
M_PIN22: J7.2 U6.22 | length 1019.8
  Top Layer w10: J7.2 708.12,1018.81 708.12,1593.4 v1(760.88,1646.16) ; U6.22 v1(976.42,1606.79)
  Signal Layer 2 w10: v1(760.88,1646.16) 800.25,1606.79 v1(976.42,1606.79)
NetC15_1: C15.1 C16.1 J2.1 J4.2 U6.12 | length 926.8
  Top Layer w10: C15.1@87.14,1598.71 C15.1@90.6,1602.17 ; C16.1@90.6,1646.16 U6.12
  Top Layer w15: C15.1@90.6,1602.17 C16.1@90.6,1646.16
  Top Layer w20: v1(53.71,1570) 82.42,1598.71 C15.1@87.14,1598.71 ; v1(196.1,1286.15) 196.1,1282.92 J4.2 302.28,1176.74 302.28,1085.48 J2.1 ; J4.2@283.19,1186.15 ccw(c259.81,1186.15) 276.34,1202.68 ccw(c292.87,1219.21) J4.2@292.87,1195.83 ; 297.69,1159.1 cw(c312.72,1167.78) J4.2@299.98,1179.57 ; J4.2@286.02,1179.3 cw(c246.78,1140.05) 302.28,1140.05 ccw(c246.78,1140.05) J4.2@286.02,1179.3
  Signal Layer 2 w20: v1(53.71,1570) 53.71,1428.54 v1(196.1,1286.15)
NetC17_1: C17.1 C18.1 L7.2 R23.1 R24.2 | length 498.3
  Top Layer w10: L7.2 695.4,707.83 732.19,671.04 732.19,534.86 C17.1 R24.2
  Top Layer w20: R23.1 C18.1
  Top Layer w25: C18.1 524.97,678.07 554.73,707.83 L7.2
NetC17_2: C17.2 R24.1 R27.2 U11.5 | length 142.1
  Top Layer w10: U11.5 680.73,454.53 R27.2 C17.2 R24.1
NetD9_A: D9.A D10.A D11.A D12.A J3.2 | length 504.7
  Top Layer w10: D10.A D11.A D12.A D9.A
  Top Layer w15: D10.A 1318.68,1131.15 1392.48,1057.34 1392.48,994.05 J3.2 ; 1392.48,1004.51 ccw(c1427.35,1004.51) J3.2@1402.69,979.86 ; 1392.48,1040.72 ccw(c1463.56,1040.72) J3.2@1413.3,990.46
NetD9_K: D9.K R21.1 | length 120.7
  Top Layer w10: R21.1 D9.K
NetD10_K: D10.K R20.1 | length 120.8
  Top Layer w10: R20.1 D10.K
NetD11_K: D11.K R19.1 | length 122.2
  Top Layer w10: R19.1 1168.73,1184.53 D11.K
NetD12_K: D12.K R18.1 | length 120.7
  Top Layer w10: R18.1 D12.K
NetD13_1: D13.1 R16.2 | length 132.1
  Top Layer w10: R16.2@1050.29,1341.42 1166.97,1341.42 D13.1@1170.9,1345.34 ; D13.1@1165.24,1338.38 D13.1@1172.2,1345.34
NetD13_2: D13.2 D13.4 J5.2 | length 603.6
  Top Layer w10: D13.4@1233.89,1380.78 1233.89,1345.34 v1@1267.94,1345.34 ; 1266.73,1004.38 ccw(c1304.15,1004.38) J5.2@1277.69,977.92 ; 1266.73,1028.52 ccw(c1328.29,1028.52) J5.2@1284.76,984.99 ; 1266.73,1052.66 ccw(c1352.43,1052.66) J5.2@1291.83,992.06 ; J5.2@1268.18,987.98 ccw(c1261.49,991.16) 1266.73,996.39 ; v1(1269.4,1069.37) 1266.73,1066.7 1266.73,996.4 ; J5.2@1275.15,994.94 cw(c1271.97,1001.63) 1266.73,996.39 ; J5.2 1266.73,996.4
  Signal Layer 2 w10: v1(1269.4,1069.37) v1(1269.4,1345.34)
NetD13_3: D13.3 R17.2 | length 123.3
  Top Layer w10: R17.2 1168.84,1382.83 D13.3@1170.9,1380.78 ; D13.3@1170.15,1382.83 D13.3@1172.2,1380.78
NetD19_K: D19.K R28.1 | length 120.7
  Top Layer w10: R28.1 D19.K
NetD20_K: D20.K R29.2 | length 120.7
  Top Layer w10: R29.2 D20.K
NetJ6_2: J6.2 U13.11 | length 601.8
  Top Layer w10: U13.11 1076.41,518.13 1129.67,571.39 1267.53,571.39 1280.61,558.3 1372.12,558.3 ; 1316.09,558.3 cw(c1316.09,473.18) J6.2@1376.28,533.37 ; 1340.23,558.3 cw(c1340.23,497.32) J6.2@1383.35,540.44 ; 1364.38,558.3 cw(c1364.38,521.46) J6.2@1390.42,547.51 ; J6.2@1373.47,550.2 ccw(c1367.12,553.3) 1372.12,558.3 ; J6.2@1380.21,556.94 cw(c1377.11,563.29) 1372.12,558.3 ; J6.2 1372.12,558.3
NetJ14_2: J14.2 TP1.1 U13.30 | length 1324.2
  Top Layer w10: J14.2@455.79,813.23 cw(c439.25,793.28) 465.17,793.28 cw(c491.08,793.28) J14.2@474.54,813.23 ; J14.2 465.17,764.65 484.06,745.75 724.23,745.75 786.12,683.86 786.12,621.99 1068.78,339.34 1068.78,211.99 v1(1096.09,184.68) 1155.15,125.62 U13.30
  Bottom Layer w10: TP1.1 1056.72,145.31 v1(1096.09,184.68)
NetJ15_2: J15.2 TP2.1 U13.31 | length 1057.1
  Top Layer w10: J15.2@742.04,814.15 cw(c716.97,789.08) 752.42,789.08 cw(c787.87,789.08) J15.2@762.8,814.15 ; J15.2 752.42,761.89 815,699.31 815,618.57 1089.02,344.55 1089.02,227.38 v1(1151,165.4) 1174.83,141.57 U13.31
  Bottom Layer w10: v1(1151,165.4) 1174.83,141.57 TP2.1
NetJ17_2: J17.2 U13.14 | length 977.5
  Top Layer w10: v1(851,632.06) 851,820.68 872.16,841.83 872.16,842.65 897.21,867.71 v1(940,867.71) ; v1(952.96,342.56) U13.14 ; v1(1073.62,944.48) 1091.5,944.48 ; J17.2@1095.92,974.7 cw(c1073.43,962.56) 1091.5,944.48 ; 1101,953.98 ccw(c1085.76,969.21) J17.2@1104.72,979.45 ; J17.2@1104.54,967.64 cw(c1102.76,961.82) 1108.84,961.82 ; J17.2 1108.84,961.82 ; J17.2@1113.14,967.64 ccw(c1114.92,961.82) 1108.84,961.82 ; 1091.5,944.48 1108.84,961.82
  Signal Layer 2 w10: v1(851,632.06) 851,531.66 952.96,429.7 v1(952.96,342.56) ; v1(940,867.71) 975.38,867.71 1052.16,944.48 v1(1073.62,944.48)
NetJ18_2: J18.2 R30.1 | length 911.3
  Top Layer w10: v1(890.53,733.01) 890.53,568.5 955.63,503.4 R30.1 ; J18.2@978.79,994.69 ccw(c960.09,1030.4) 1000.4,1030.4 ; J18.2@983.43,985.83 ccw(c968.74,1013.88) 1000.4,1013.88 ; J18.2 1000.4,996.48 ; J18.2@988.07,976.97 ccw(c977.39,997.35) 1000.4,997.35 ; J18.2@991.83,994.97 ccw(c995.05,1001.83) 1000.4,996.48 ; J18.2@998.9,987.91 cw(c1005.76,991.12) 1000.4,996.48 ; v1@1011.18,1041.18 v1(1015,1045) 1000.4,1030.4 ; 1000.4,996.48 1000.4,1030.4
  Signal Layer 2 w10: v1(890.53,733.01) 890.53,860.2 930.41,900.09 979.48,900.09 1000.4,921.01 1000.4,1030.4 v1(1015,1045)
NetL7_1: L7.1 U11.3 | length 59.6
  Top Layer w20: U11.3 605.93,603.81 L7.1
NetR15_2: R15.2 U9.4 | length 57.3
  Top Layer w10: R15.2 U9.4
NetR18_2: R18.2 U6.7 | length 1126.4
  Top Layer w10: U6.7 v1(235.86,1843.01) ; v1(983.75,1231.15) R18.2@1010.02,1231.15
  Signal Layer 2 w10: v1(235.86,1843.01) 422.92,1843.01 922,1343.93 922,1292.9 v1(983.75,1231.15)
NetR19_2: R19.2 U6.8 | length 1145.9
  Top Layer w10: U6.8 v1(235.86,1803.64) ; v1@985.05,1184.53 R19.2
  Signal Layer 2 w10: v1(235.86,1803.64) 436.83,1803.64 895.39,1345.09 895.39,1271.59 v1(983.75,1183.23)
NetR20_2: R20.2 U6.9 | length 1168
  Top Layer w10: U6.9 v1(235.86,1764.27) ; v1(983.75,1131.15) R20.2
  Signal Layer 2 w10: v1(235.86,1764.27) 450.75,1764.27 877.39,1337.63 877.39,1237.51 v1(983.75,1131.15)
NetR21_2: R21.2 U6.10 | length 1107.7
  Top Layer w10: U6.10 v1(235.86,1724.9) ; v1(543.08,1631.77) v1(609.73,1698.42) ; v1(983.75,1281.15) R21.2
  Signal Layer 2 w10: v1(235.86,1724.9) 464.66,1724.9 543.08,1646.48 v1(543.08,1631.77) ; v1(609.73,1698.42) 609.73,1681.66 940,1351.39 940,1324.9 v1@974.95,1289.95
NetR25_2: R25.2 U9.2 | length 57.3
  Top Layer w10: R25.2 U9.2
NetR28_2: R28.2 U9.8 | length 2035.4
  Top Layer w10: U9.8 754.09,154.83 819.73,220.47 819.73,288.79 800.8,307.72 800.8,581.86 758.72,623.94 v1(758.72,670.71) ; v1(760.88,1567.42) 760.88,1411 847.03,1324.85 847.03,1194.09 869.17,1171.95 869.17,1111.98 904,1077.15 904,977.18 854.16,927.34 854.16,849.29 823.23,818.36 v1(823.23,735.22) ; v1(996,1536) 996,1506.11 R28.2
  Signal Layer 2 w10: v1(758.72,670.71) v1(823.23,735.22) ; v1(760.88,1567.42) 792.3,1536 v1(996,1536)
NetR29_1: R29.1 U13.10 | length 1468
  Top Layer w10: v1@987.75,1437.91 R29.1 ; U13.10 1096.09,511.83 1131.9,547.64 v1(1160.65,547.64)
  Signal Layer 2 w10: v1(980.63,1437.91) 1255.34,1437.91 1295.47,1397.79 1295.47,624.1 1219.01,547.64 v1(1160.65,547.64)
NetR30_2: R30.2 U13.12 | length 73.7
  Top Layer w10: R30.2 1035.12,466.2 1056.72,444.6 U13.12
NetR32_2: R32.2 U9.9 | length 61
  Top Layer w10: U9.9 665.6,174.51 R32.2
NetSW2_1: SW2.1 SW2.2 U6.32 | length 558.7
  Top Layer w10: U6.32 984.86,2000.49 1003.24,1982.11 1003.24,1844.74 SW2.2@1044.8,1803.18 ; SW2.2@1069.2,1827.42 SW2.1@1328.41,1827.42
NF1: C13.2 J8.1 U6.4 | length 928
  Top Layer w10: v1(35.07,1935.94) 60.25,1961.12 C13.2 U6.4
  Signal Layer 2 w10: v1@32.55,1933.42 25,1925.87 25,1240.57 J8.1
NF2: C14.2 J8.2 U6.5 | length 973.8
  Top Layer w10: U6.5 C14.2 25,1866.75 25,1267.69 55.54,1237.15 143.86,1237.15 188.43,1192.58 J8.2
RESET: J6.1 J10.12 SW1.1 SW1.2 U6.33 | length 2544.3
  Top Layer w10: U6.33 1008.05,2039.86 1038.19,2070 SW1.2 1079.91,2053.56 1133.43,2053.56 1144.65,2042.35 1253.57,2042.35 1264.79,2053.56 1299.69,2053.56 SW1.1 1369.51,2070 v1(1369.51,2016.32) ; J6.1@1376.28,603.5 ccw(c1351.21,628.57) 1386.66,628.57 ccw(c1422.11,628.57) J6.1@1397.05,603.5 ; J6.1 v1(1386.66,640.64)
  Signal Layer 2 w10: v1(1369.51,2016.32) 1395,1990.83 1395,1857.4 1464.98,1787.42 1621.29,1787.42 1669.91,1738.8 1669.91,1193.09 J10.12 1565,1088.18 1565,608.09 1539.77,582.86 1483.27,582.86 1425.5,640.64 v1(1386.66,640.64)
RTS: U13.16
RX_LED: R16.1 U6.31 | length 1433
  Top Layer w10: U6.31 v1(976.42,1961.12) ; R16.1@1014.19,1334.53 1014.31,1334.53 1033.84,1315 v1(1400.3,1315)
  Signal Layer 2 w10: v1(976.42,1961.12) 1197.29,1961.12 1423.03,1735.38 1423.03,1337.74 v1(1400.3,1315)
RXD: J13.1 J15.1 U6.20 | length 1508.3
  Top Layer w10: J13.1@605.04,870.15 ccw(c631.45,896.57) 631.45,859.2 ; J13.1 623.5,859.2 ; J13.1@612.11,877.22 ccw(c655.6,920.71) 655.6,859.2 ; J13.1@615.11,860.65 cw(c618.28,853.99) 623.49,859.2 ; J13.1@619.18,884.29 ccw(c679.74,944.85) 679.74,859.2 ; J13.1@622.05,867.59 ccw(c628.71,864.42) 623.49,859.2 ; 681.47,859.2 ccw(c681.47,944.85) J15.1@742.04,884.29 ; 705.62,859.2 ccw(c705.62,920.71) J15.1@749.11,877.22 ; 729.76,859.2 ccw(c729.76,896.57) J15.1@756.18,870.15 ; J15.1@748.66,870.15 ccw(c775.08,896.57) 775.08,859.2 ; J15.1@755.73,877.22 ccw(c799.22,920.71) 799.22,859.2 ; J15.1@762.8,884.29 ccw(c823.37,944.85) v1@823.37,859.2 ; v1(826.31,859.2) 623.5,859.2 ; v1(881.05,913.95) 922,954.9 922,1326.25 815,1433.25 815,1505 838.05,1528.05 U6.20
  Signal Layer 2 w10: v1(826.31,859.2) v1(881.05,913.95)
RXD_RPI: J10.10 J13.2 | length 1420.2
  Top Layer w10: J13.2@598.41,814.15 cw(c573.34,789.08) 608.79,789.08 cw(c644.25,789.08) J13.2@619.18,814.15 ; v1(608.79,771.57) J13.2 ; v1(968.92,925.59) 984.54,909.97 1404.06,909.97 1476.11,982.02 1540.06,982.02 1565,1006.96 1565,1188.18 J10.10
  Signal Layer 2 w10: v1(608.79,771.57) 776.44,771.57 930.46,925.59 v1(968.92,925.59)
SCL_RPI: J10.5 U6.25 | length 854
  Top Layer w10: U6.25@948.04,1717.38 1385.36,1717.38 1450,1652.74 1450,1600 1470,1580 1534.79,1580 1561.82,1552.97 1561.82,1485 J10.5
SDA_RPI: J10.3 U6.23 | length 726.4
  Top Layer w10: U6.23 976.42,1646.16 1022.58,1692.33 1379.31,1692.33 1423.03,1648.6 1423.03,1582.26 1472.11,1533.18 J10.3
SPI1_CLK: J10.23 U6.28 | length 1853.4
  Top Layer w10: U6.28 v1(976.42,1843.01) ; v1(1375,857.56) 1424.65,807.91 1460.56,807.91 1486.06,782.41 1537.59,782.41 1559.68,760.32 1559.68,582.86 J10.23
  Signal Layer 2 w8: v1(976.42,1843.01) 1251.76,1843.01 1359.47,1735.31 1359.47,873.1 v1(1375,857.56)
SPI1_MISO: J10.21 U6.26 | length 1611.7
  Top Layer w10: U6.26 v1(976.42,1764.27)
  Signal Layer 2 w8: v1(976.42,1764.27) 984.27,1772.13 1283.05,1772.13 1331.47,1723.71 1331.47,845.84 1510,667.31 J10.21
SPI1_MOSI: J10.19 U6.27 | length 1576.1
  Top Layer w10: U6.27 v1(976.42,1803.64)
  Signal Layer 2 w8: v1(976.42,1803.64) 995.68,1822.9 1252.07,1822.9 1345.47,1729.51 1345.47,851.64 1463.93,733.18 J10.19
SWCLK: J18.1 U6.2 | length 1842.4
  Top Layer w10: U6.2 174.78,2032.07 672.93,2032.07 810,1895 810,1525.46 797,1512.46 797,1425.79 895.39,1327.4 v1(895.39,1122.15) ; J18.1 1034.97,996.89 1055.79,1017.7 ; J18.1@1039.39,983.25 cw(c1060.39,990.76) 1044.62,1006.53 ; J18.1@1048.8,986.62 cw(c1076.85,996.64) 1055.79,1017.7 ; v1(1050.21,1045.91) 1055.79,1040.32 1055.79,1017.7
  Signal Layer 2 w10: v1(895.39,1122.15) 918.81,1122.15 962.66,1078.3 1017.81,1078.3 v1(1050.21,1045.91)
SWCLK_OB: J11.4 TP6.1 U13.37 | length 913.6
  Top Layer w10: v1(931.76,628.89) 931.76,632.06 992.7,693 1052.2,693 J11.4 ; v1(1151,257.11) 1241.61,166.5 1264.96,166.5 1285.75,145.71 U13.37
  Signal Layer 2 w10: v1(931.76,628.89) 904.7,601.83 904.7,503.42 v1(1151,257.11)
SWDIO: J17.1 U6.3 | length 1935
  Top Layer w10: U6.3 679.05,2000.49 792,1887.54 792,1532.91 779,1519.91 779,1418.33 871.63,1325.7 v1(871.63,1206.63) ; v1(1052.07,1097.61) 1092.32,1097.61 1143.45,1046.48 1143.45,987.03 J17.1@1148.8,981.68 ; 1143.45,1002.47 ccw(c1176.36,1002.47) J17.1@1154.72,977.67 ; 1143.45,1024.47 ccw(c1195.56,1024.47) J17.1@1161.29,985.21 ; 1143.45,1046.47 ccw(c1214.77,1046.47) J17.1@1167.87,992.74
  Signal Layer 2 w10: v1(871.63,1206.63) 980.66,1097.61 v1(1052.07,1097.61)
SWDIO_OB: J11.2 TP4.1 U13.34 | length 892.2
  Top Layer w10: v1(931.76,585.05) 954.31,562.5 1046.39,562.5 1079.91,596.02 1079.91,670.71 J11.2 ; v1(1116.9,332.86) 1116.9,238.11 1233.89,121.12 U13.34
  Signal Layer 2 w10: v1(931.76,585.05) 931.76,501.81 1100.71,332.86 v1(1116.9,332.86)
SWO: U13.13
TX_LED: R17.1 U6.30 | length 1287.8
  Top Layer w10: U6.30 v1(976.42,1921.75) ; R17.1@1014.19,1387.91 1014.31,1387.91 1033.56,1407.16 v1(1397.13,1407.16)
  Signal Layer 2 w10: v1(976.42,1921.75) 1214.03,1921.75 1397.13,1738.66 v1(1397.13,1407.16)
TXD: J10.8 J14.1 U6.18 | length 1764.1
  Top Layer w10: J14.1 535.35,873.9 570.88,909.43 824.53,909.43 v1(827.96,906) ; J14.1@475.55,863.52 cw(c500.62,838.45) 500.62,873.9 cw(c500.62,909.36) J14.1@475.55,884.29 ; U6.18 U6.18@940,1449.31 ; U6.18@950,1449.31 950,1424.35 v1(967.19,1407.16) 958,1397.97 958,1050.36 v1@965.62,1042.74 ; v1(1269.4,1380.78) 1562.4,1380.78 J10.8
  Signal Layer 2 w10: v1(827.96,906) 832.82,906 v1(967.19,1040.37) ; v1(967.19,1407.16) 990.66,1407.16 1000.4,1416.91 1233.27,1416.91 v1(1269.4,1380.78)
V_LIPO_BAT: C19.1 J1.1 J12.1 Q1.D U9.10 | length 977.6
  Top Layer w20: J1.1 239.84,918.02 281.27,918.02 314.66,884.63 J12.1@314.66,833.94 ; J12.1 389.38,826.69 435.23,780.84 435.23,471.05 533.62,372.66 533.62,346.08 C19.1 543.57,341.02 Q1.D@576.18,308.41 ; 590.8,199.34 Q1.D@590.8,310.43
VBAT: C20.1 D15.2 Q1.S R22.1 U11.1 U11.4 | length 507.7
  Top Layer w10: U11.4 612.71,467.35 612.71,485.54 628.21,501.04 667.19,501.04 680.73,514.59 U11.1
  Top Layer w20: U11.4@601.4,451.04 601.24,450.88 582.02,450.88 C20.1 552.04,420.9 552.04,396.8 600.39,348.44 Q1.S D15.2@753.33,348.44 ; D15.2 R22.1
VRPI: D16.1 J10.2 J10.4 | length 206.8
  Top Layer w20: J10.4 J10.2 D16.1
VUSB: D14.1 J9.1 TP11.1 | length 247.5
  Top Layer w15: J9.1@201.34,566.46 201.34,626.34 221.6,646.6 351.54,646.6 D14.1
  other v1: 267.93,646.6
pads on no net: D15.NC J9.4 J9.6 J10.1 J10.7 J10.11 J10.13 J10.16 J10.17 J10.18 J10.22 J10.26 J11. J11.6 J12.0 M1.1 M2.1 M3.1 U9.5 U9.6 U13.2 U13.3 U13.4 U13.5 U13.6 U13.15 U13.18 U13.19 U13.20 U13.21 U13.22 U13.25 U13.26 U13.27 U13.28 U13.29 U13.38 U13.39 U13.40 U13.41 U13.42 U13.43 U13.45 U13.46

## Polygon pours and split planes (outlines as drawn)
GND on Signal Layer 1 "TopLayer-PWM4 1" (solid, remove dead copper, pour order 16): -116.38,2102.04 -116.38,-194.39 1223.73,-194.39 1796.26,-194.39 1796.26,2231.02 81.81,2231.02 81.81,2221.58 -116.38,2221.58 -116.38,2101.55
GND on Bottom Layer "TopLayer-PWM4 1" (solid, remove dead copper, pour order 15): -78.62,2123.62 -78.62,-172.81 1261.49,-172.81 1834.03,-172.81 1834.03,2252.6 119.57,2252.6 119.57,2243.16 -78.62,2243.16 -78.62,2123.13
EARTH on Signal Layer 2 "TopLayer-PWM4 1" (solid, remove dead copper, pour order 10): -87.37,761.19 212.63,761.19 322.63,651.19 357.63,616.19 357.63,296.19 22.63,-38.81 -57.37,-38.81 -87.37,-8.81 -87.37,761.19
5V on Signal Layer 2 "TopLayer-PWM4 1" (solid, remove dead copper, pour order 12): 353.79,685.76 441.22,685.76 608.52,535.76 608.52,449.04 829.05,449.04 887.35,396.76 944.74,345.31 944.74,75.76 944.74,12.22 870.62,-54.24 6.24,-54.24 -127.6,65.76 191.76,352.1 191.76,370.76 267.47,438.65 267.47,655.76 300.93,685.76 353.79,685.76
GND on Signal Layer 2 "TopLayer-PWM4 1" (solid, remove dead copper, pour order 13): -269.24,2349.81 1745.76,2349.81 1950.76,2349.81 1955.76,2344.81 1955.76,57.41 1633.16,-265.19 1315.98,-265.19 1160.98,-110.19 1160.98,504.66 921.66,743.98 413.38,743.98 217.76,548.36 -67.79,548.36 -334.24,814.81 -334.24,2284.81 -269.24,2349.81
3V4_SEGGER on Signal Layer 2 "TopLayer-PWM4 1" (solid, remove dead copper, pour order 9): 748,-67.63 1413,-67.63 1528,47.37 1528,620.57 1416.2,732.37 849.71,732.37 783,665.66 663,545.66 663,132.37 663,-12.63 718,-67.63 748,-67.63
3V4 on Signal Layer 2 "TopLayer-PWM4 1" (solid, remove dead copper, pour order 14): 166.99,1504.04 166.99,569.35 543.5,192.84 644.5,91.84 914.99,91.84 914.99,318.3 1021.22,424.53 1041.54,444.85 1371.29,444.85 1454.99,528.55 1454.99,642.84 1454.99,1481.79 1361.85,1574.92 1280.4,1656.38 1074.99,1656.38 1023.06,1656.38 899.99,1533.3 804.99,1438.3 804.99,1022.84 659.95,1022.84 604.99,1077.8 574.99,1107.8 574.99,1371.29 418.44,1527.84 219.99,1527.84
GND on Top Layer "TopLayer-PWM4 1" (solid, remove dead copper, pour order 11): -383.08,2459.95 -383.08,-175.05 1951.92,-175.05 2056.92,-175.05 2056.92,2414.95 2056.92,2459.95 -383.08,2459.95

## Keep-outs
Keep-Out Layer:
  lines w0.5: -2704.19,-36.7 -2397.68,269.81 -2397.68,511.26 ; -2704.22,56.81 -2698.49,56.81 ; -2583.98,2029.25 -1749.93,2029.25 ; -2555.6,-96.73 -2555.6,-86.09 ; -2124.42,863.18 -1747.01,863.18 -1714.22,895.97 -1714.22,1303.7 -1677.24,1340.67 -1417.95,1340.67 -1386.05,1308.77 -1386.05,630.37 ; -2124.42,863.27 -2160.18,827.51 -2224.22,827.51 -2224.22,1230.13 -2297.78,1303.7 -2385.3,1303.7 -2414.22,1274.78 -2414.22,728.74 -2514.69,628.27 ; -1918.72,-96.24 -1818.83,-96.24 -1818.83,238.66 -1818.83,284.11 -1818.83,362.67 -1802.9,378.59 -1722.18,459.32 -1557.11,459.32 -1404.99,611.43 -1386.05,630.37 ; -1818.83,103.27 -1999.22,103.27 -2024.76,128.81 -2024.76,249.64 -2053.39,278.27 -2202.47,278.27 -2242.49,318.29 -2242.49,447.93 -2305.82,511.26 -2397.68,511.26 ; -1349.22,-96.73 -1710.85,-96.73 ; -2704.22,-96.73 -1011.3,-96.73 ; -2704.22,-96.73 -2704.22,2029.25 ; -2704.22,-96.73 -1710.85,-96.73 ; -2704.22,-96.73 -2704.22,198.27 -2704.22,628.27 ; -2704.22,628.27 -2704.22,2029.25 ; -2704.22,628.27 -2514.69,628.27 ; -2704.22,2029.25 -1011.3,2029.25 ; -2704.22,2029.25 -1011.3,2029.25 ; -2514.69,628.27 -2397.68,511.26 ; -1710.85,-96.73 -1710.85,-96.73 ; -1710.85,-96.73 -1710.85,-96.73 ; -1386.05,630.37 -1329.22,573.54 -1329.22,520.85 -1329.22,428.27 -1329.22,-93.03 -1332.92,-96.73 -1011.3,-96.73 ; -1011.3,-96.73 -1011.3,2029.25 ; -1011.3,-96.73 -1011.3,2029.25
  lines w20: -2704.22,2029.25 -2704.22,-96.73 -1011.3,-96.73 -1011.3,2029.27 ; -2635.96,5026.14 -2635.96,2900.15 -943.04,2900.15 -943.04,5026.14
  lines w34: -2704.22,2029.27 -1011.3,2029.27 ; -2635.96,5026.14 -943.04,5026.14

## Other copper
Top Layer:
  pour cut-out: 499.97,623.83 499.97,533.26 527.19,506.04 527.19,436.04 569.07,436.04 634.07,501.04 667.19,501.04 667.19,544.98 643.33,568.84 590.36,568.84 535.36,623.83
  pour cut-out: 1251.76,1040.23 1251.76,923.07 cw(c1251.76,981.65)
Signal Layer 2:
  pour cut-out: 1014.2,630 1214.2,630 1214.2,884.62 1073.62,884.62 1014.2,825.2 1014.2,630

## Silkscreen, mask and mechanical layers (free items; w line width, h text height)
Top Overlay:
  lines w25: 1125.65,1102.36 ccw(c1157.48,1102.36) 1157.48,1070.53 1314.97,1070.53 ccw(c1314.97,1102.36) 1346.79,1102.36 1346.79,1515.75 ccw(c1314.97,1515.75) 1314.97,1547.58 1157.48,1547.58 ccw(c1157.48,1515.75) 1125.65,1515.75 1125.65,1102.36
  text "+ -" at 205.92,1083.33 h50 r180
  text "+ -" at 93.43,867.46 h50 r270
Bottom Overlay:
  drawing of 952 lines, arcs and shapes, not listed
  text "J-Link OB" at 488.66,505.24 h69
  text "www.segger.com" at 737.66,452.5 h69
  text "20171016" at 735.45,88.03 h30
  text "TLL00X620205" at 735.45,43.03 h30
M2_OUTLINE:
  the board outline again, w5
M3_PANEL:
  drawing of 161 lines, arcs and shapes, not listed
  text "V-CUT" at 41.65,6462.89 h100 r90
  text "V-CUT" at 1734.56,6462.89 h100 r90
  text "V-CUT" at 1950.92,6462.89 h100 r90
  text "V-CUT" at 3643.84,6462.89 h100 r90
  text "V-CUT" at 3860.2,6462.92 h100 r90
  text "V-CUT" at 5553.11,6462.92 h100 r90
  text "V-CUT" at 6777.81,4574.4 h100
  text "V-CUT" at 6777.81,2448.39 h100
  text "V-CUT" at 6777.81,2084.37 h100
  text "V-CUT" at 6777.81,-41.61 h100
M4_NOTE:
  lines w10: 160.69,1404.04 -320.36,1404.04 -320.36,1246.54 1989.47,1246.54
  text "KEEPOUT FOR GND" at -2161.96,2751.14 h60
  text "GND" at -1989.33,1380.53 h30
  text "3V4" at -2025.67,654.35 h30
  text "EARTH" at -2614.33,360.53 h30
  text "3V4_SEGGER" at -1705.52,184.59 h30
  text "5V" at -2264.33,75.53 h30
  text "KEEPOUT FOR MID-LAYER 2" at -2554.33,-239.47 h60
M5_DIMENSION:
  text "LED" at 1724.7,1270.76 h60
  text "NFC" at -300,1245 h60
  text "EXTRA HEADER" at 282.98,1073.17 h60
  text "BATT" at -359.98,1015 h60
  text "RPI" at 1812.39,749.97 h60 r90
  text "BATT" at -359.98,745 h60
  text "J-LINK OB PROG" at 755.24,-120 h60
Mechanical 10:
  drawing of 1479 lines, arcs and shapes, not listed

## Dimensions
0,0 to 1692.91,0 on M5_DIMENSION
1692.91,2125.98 to 1692.91,0 on M5_DIMENSION
1125.65,1515.75 to 1337.47,1538.26 on M5_DIMENSION
1314.97,1547.58 to 1314.97,1070.53 on M5_DIMENSION
-320.36,1404.04 to -320.36,1246.54 on M4_NOTE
